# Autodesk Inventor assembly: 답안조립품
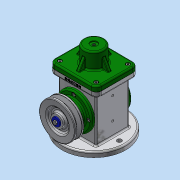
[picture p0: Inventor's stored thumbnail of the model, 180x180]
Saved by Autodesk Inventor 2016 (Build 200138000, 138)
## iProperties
Created: 2018-10
Part Number: 답안조립품
Material: 일반
Document SubType Name: Assembly
Designer: Administrator
Author: Administrator
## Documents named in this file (17)
- D:\권재형\481007V1051\답안조립품.iam
- D:\권재형\481007V1051\본체.ipt
- D:\권재형\481007V1051\편심축.ipt
- D:\권재형\481007V1051\베어링 17 x 40 x 12.ipt
- D:\권재형\481007V1051\앞커버.ipt
- D:\권재형\481007V1051\오일 실 17 30 8.ipt
- D:\권재형\481007V1051\V-벨트풀리.ipt
- D:\권재형\481007V1051\키 4 x 4 x 12.ipt
- D:\권재형\481007V1051\와셔 4x16.ipt
- D:\권재형\481007V1051\볼트 M4 x 10.ipt
- D:\권재형\481007V1051\볼트 M4 x 8.ipt
- D:\권재형\481007V1051\뒤커버.ipt
- D:\권재형\481007V1051\슬라이더.ipt
- D:\권재형\481007V1051\덮개.ipt
- D:\권재형\481007V1051\클레비스 핀 6 x 22.ipt
- 클레비스 핀 6 x 22.ipt
- D:\권재형\481007V1051\링크.ipt
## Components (1 placed, 1 different names)
1. V-벨트풀리:1
